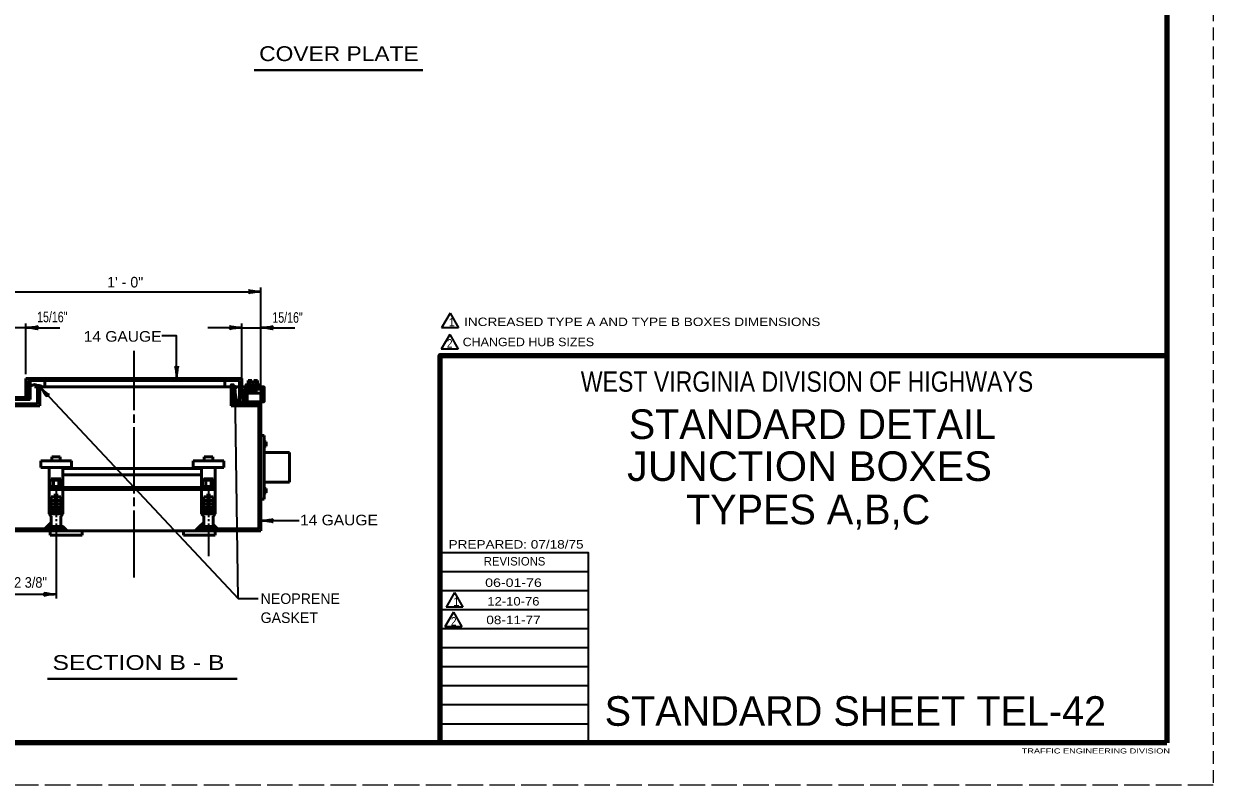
# Model space of a CAD drawing. Extents: x -1 to 679, y 0 to 440.
# Drawn here: x 397.8 to 678.8, y 0.4 to 180.3 of the extents above; entities that cross this region are included whole.
import ezdxf
from ezdxf.enums import TextEntityAlignment as Align

# ---------------------------------------------------------------- set-up
doc = ezdxf.new("R2010")
doc.units = 0
doc.linetypes.add('LONG_DASHED', pattern=[7.5, 6, -1.5])
doc.linetypes.add('MEDIUM_DASHED', pattern=[4.5, 3, -1.5])
doc.layers.add('1', color=7, linetype='Continuous', lineweight=53)
doc.layers.add('61', color=7, linetype='Continuous', lineweight=35)

msp = doc.modelspace()

# ---------------------------------------------------------------- linework, layer by layer
at = {"layer": '1', "linetype": 'MEDIUM_DASHED', "lineweight": 13}
msp.add_line((678.783, 440.398), (678.763, 0.378), dxfattribs=at)
at = {"layer": '1', "lineweight": 40}
for p, q in [((452.219, 169.353), (492.059, 169.353)), ((403.381, 25.473), (448.187, 25.473))]:
    msp.add_line(p, q, dxfattribs=at)
at = {"layer": '1', "lineweight": 35}
for p, q in [((393.265, 116.975), (453.765, 116.975)), ((453.765, 92.975), (453.765, 117.975)), ((498.479, 111.937), (496.479, 108.472)), ((498.479, 111.937), (500.479, 108.472)), ((398.265, 108.475), (393.265, 108.475)), ((398.265, 97.475), (398.265, 109.475)), ((398.265, 108.475), (406.265, 108.475)), ((449.265, 108.475), (441.265, 108.475)), ((449.265, 96.475), (449.265, 109.475)), ((449.265, 108.475), (453.765, 108.475)), ((453.765, 108.475), (461.765, 108.475)), ((498.402, 106.871), (496.402, 103.407)), ((500.479, 108.472), (496.479, 108.472)), ((498.402, 106.871), (500.402, 103.407)), ((423.765, 102.975), (423.765, 88.975)), ((500.402, 103.407), (496.402, 103.407)), ((423.765, 87.975), (423.765, 85.975)), ((423.765, 84.975), (423.765, 69.309)), ((405.39, 70.225), (405.39, 64.475)), ((423.765, 68.309), (423.765, 66.309)), ((441.39, 70.225), (441.39, 63.725)), ((423.765, 65.309), (423.765, 49.475)), ((405.39, 64.475), (405.39, 63.725)), ((405.39, 63.225), (405.39, 62.725)), ((405.39, 62.225), (405.39, 61.475)), ((441.39, 63.225), (441.39, 62.725)), ((441.39, 62.225), (441.39, 54.475)), ((453.765, 62.888), (462.798, 62.888)), ((405.39, 61.475), (405.39, 44.475)), ((531.163, 50.798), (496.183, 50.798)), ((393.265, 45.475), (405.39, 45.475)), ((531.163, 46.298), (496.183, 46.298)), ((499.52, 45.866), (497.52, 42.402)), ((499.52, 45.866), (501.52, 42.402)), ((448.434, 44.474), (453.113, 44.474)), ((501.52, 42.402), (497.52, 42.402)), ((531.163, 41.798), (496.183, 41.798)), ((499.278, 41.265), (497.278, 37.801)), ((499.278, 41.265), (501.278, 37.801)), ((531.163, 37.278), (496.183, 37.278)), ((501.278, 37.801), (497.278, 37.801)), ((531.163, 32.798), (496.183, 32.798)), ((531.163, 28.318), (496.183, 28.318)), ((531.163, 23.818), (496.183, 23.818)), ((531.163, 19.318), (496.183, 19.318)), ((531.163, 14.798), (496.183, 14.798))]:
    msp.add_line(p, q, dxfattribs=at)
at = {"layer": '1'}
for p, q in [((398.265, 96.475), (449.265, 96.475)), ((398.265, 96.475), (398.265, 91.975)), ((398.765, 95.975), (448.765, 95.975)), ((398.765, 95.975), (398.765, 91.975)), ((399.265, 95.975), (399.265, 91.475)), ((399.515, 96.475), (399.515, 95.975)), ((400.765, 96.475), (400.765, 95.975)), ((402.015, 96.475), (402.015, 95.975)), ((402.765, 95.975), (402.765, 94.478)), ((403.265, 96.475), (403.265, 95.975)), ((404.515, 96.475), (404.515, 95.975)), ((405.765, 96.475), (405.765, 95.975)), ((407.015, 96.475), (407.015, 95.975)), ((408.265, 96.475), (408.265, 95.975)), ((409.515, 96.475), (409.515, 95.975)), ((410.765, 96.475), (410.765, 95.975)), ((412.015, 96.475), (412.015, 95.975)), ((413.265, 96.475), (413.265, 95.975)), ((414.515, 96.475), (414.515, 95.975)), ((415.765, 96.475), (415.765, 95.975)), ((417.015, 96.475), (417.015, 95.975)), ((418.265, 96.475), (418.265, 95.975)), ((419.515, 96.475), (419.515, 95.975)), ((420.765, 96.475), (420.765, 95.975)), ((422.015, 96.475), (422.015, 95.975)), ((423.265, 96.475), (423.265, 95.975)), ((424.515, 96.475), (424.515, 95.975)), ((425.765, 96.475), (425.765, 95.975)), ((427.015, 96.475), (427.015, 95.975)), ((428.265, 96.475), (428.265, 95.975)), ((429.515, 96.475), (429.515, 95.975)), ((430.765, 96.475), (430.765, 95.975)), ((432.015, 96.475), (432.015, 95.975)), ((433.265, 96.475), (433.265, 95.975)), ((434.515, 96.475), (434.515, 95.975)), ((435.765, 96.475), (435.765, 95.975)), ((437.015, 96.475), (437.015, 95.975)), ((438.265, 96.475), (438.265, 95.975)), ((439.515, 96.475), (439.515, 95.975)), ((440.765, 96.475), (440.765, 95.975)), ((442.015, 96.475), (442.015, 95.975)), ((443.265, 96.475), (443.265, 95.975)), ((444.515, 96.475), (444.515, 95.975)), ((445.265, 95.975), (445.265, 94.478)), ((445.765, 96.475), (445.765, 95.975)), ((447.015, 96.475), (447.015, 95.975)), ((448.265, 96.475), (448.265, 95.975)), ((448.765, 95.975), (448.765, 90.975)), ((449.265, 96.475), (449.265, 91.475)), ((450.765, 94.975), (450.765, 95.975)), ((450.765, 95.975), (451.64, 95.975)), ((451.203, 95.975), (451.203, 94.975)), ((451.64, 95.975), (451.64, 95.475)), ((453.015, 95.975), (452.14, 95.975)), ((452.14, 95.975), (452.14, 95.475)), ((452.578, 95.975), (452.578, 94.975)), ((453.015, 94.975), (453.015, 95.975)), ((401.515, 94.475), (400.265, 94.475)), ((401.015, 94.475), (401.015, 90.475)), ((401.515, 94.475), (401.515, 89.975)), ((402.015, 94.478), (448.765, 94.478)), ((447.265, 94.562), (447.765, 94.562)), ((447.265, 94.062), (447.765, 94.062)), ((447.765, 94.562), (447.765, 94.062)), ((450.515, 92.975), (453.765, 92.975)), ((451.64, 95.475), (452.14, 95.475)), ((453.515, 94.975), (453.515, 94.475)), ((401.515, 89.975), (393.765, 89.975)), ((399.265, 91.975), (395.265, 91.975)), ((399.265, 91.475), (395.265, 91.475)), ((401.015, 90.475), (395.265, 90.475)), ((398.515, 90.475), (398.515, 89.975)), ((400.015, 90.475), (400.015, 89.975)), ((453.265, 89.975), (446.765, 89.975)), ((453.765, 90.975), (447.265, 90.975)), ((453.765, 90.475), (447.265, 90.475)), ((448.765, 90.475), (448.765, 89.975)), ((449.265, 90.975), (449.265, 90.475)), ((450.265, 90.475), (450.265, 89.975)), ((450.765, 90.975), (450.765, 90.475)), ((451.765, 90.475), (451.765, 89.975)), ((452.265, 90.975), (452.265, 90.475)), ((453.103, 90.475), (453.103, 89.975)), ((453.265, 89.975), (453.265, 60.975)), ((453.765, 88.975), (453.265, 88.975)), ((453.765, 87.475), (453.265, 87.475)), ((453.765, 85.975), (453.265, 85.975)), ((453.765, 84.475), (453.265, 84.475)), ((453.765, 82.975), (453.265, 82.975)), ((454.515, 82.975), (453.765, 82.975)), ((454.515, 82.975), (454.515, 67.975)), ((453.765, 81.475), (453.265, 81.475)), ((453.765, 79.975), (453.265, 79.975)), ((454.515, 81.475), (455.015, 81.475)), ((454.515, 80.475), (455.015, 80.475)), ((454.515, 78.975), (460.515, 78.975)), ((455.015, 81.475), (455.015, 80.475)), ((460.515, 78.975), (460.515, 71.975)), ((401.765, 76.975), (409.015, 76.975)), ((401.765, 76.975), (401.765, 75.475)), ((404.39, 76.975), (404.39, 77.975)), ((404.39, 77.975), (406.39, 77.975)), ((406.39, 76.975), (406.39, 77.975)), ((409.015, 76.975), (409.015, 75.475)), ((437.765, 76.975), (445.015, 76.975)), ((437.765, 76.975), (437.765, 75.475)), ((440.39, 76.975), (440.39, 77.975)), ((440.39, 77.975), (442.39, 77.975)), ((442.39, 76.975), (442.39, 77.975)), ((445.015, 76.975), (445.015, 75.475)), ((453.765, 78.475), (453.265, 78.475)), ((453.765, 76.975), (453.265, 76.975)), ((401.765, 75.475), (409.015, 75.475)), ((403.765, 64.475), (403.765, 75.475)), ((407.015, 64.475), (407.015, 75.475)), ((407.015, 75.238), (439.765, 75.238)), ((407.015, 73.738), (439.765, 73.738)), ((437.765, 75.475), (445.015, 75.475)), ((439.765, 64.475), (439.765, 75.475)), ((443.015, 64.475), (443.015, 75.475)), ((453.765, 75.475), (453.265, 75.475)), ((453.765, 73.975), (453.265, 73.975)), ((403.765, 70.725), (407.015, 70.725)), ((404.015, 72.475), (404.265, 72.725)), ((404.015, 72.475), (406.765, 72.475)), ((404.015, 70.975), (404.015, 72.475)), ((404.015, 70.975), (406.765, 70.975)), ((404.265, 72.725), (406.515, 72.725)), ((404.765, 70.975), (404.765, 72.475)), ((406.015, 70.975), (406.015, 72.475)), ((406.515, 72.725), (406.765, 72.475)), ((406.765, 70.975), (406.765, 72.475)), ((407.015, 70.725), (440.015, 70.725)), ((439.765, 70.725), (443.015, 70.725)), ((440.015, 72.475), (440.265, 72.725)), ((440.015, 72.475), (442.765, 72.475)), ((440.015, 70.975), (440.015, 72.475)), ((440.015, 70.975), (442.765, 70.975)), ((440.265, 72.725), (442.515, 72.725)), ((440.765, 70.975), (440.765, 72.475)), ((442.015, 70.975), (442.015, 72.475)), ((442.515, 72.725), (442.765, 72.475)), ((442.765, 70.975), (442.765, 72.475)), ((453.765, 72.475), (453.265, 72.475)), ((453.765, 70.975), (453.265, 70.975)), ((454.515, 71.975), (460.515, 71.975)), ((454.515, 70.475), (455.015, 70.475)), ((455.015, 70.475), (455.015, 69.475)), ((403.765, 70.225), (407.015, 70.225)), ((404.265, 65.475), (404.265, 68.475)), ((404.265, 68.475), (406.515, 68.475)), ((404.265, 67.675), (406.515, 67.675)), ((404.89, 68.875), (405.89, 68.875)), ((404.89, 68.075), (405.89, 68.075)), ((406.515, 65.475), (406.515, 68.475)), ((407.015, 70.225), (440.015, 70.225)), ((439.765, 70.225), (443.015, 70.225)), ((440.265, 65.475), (440.265, 68.475)), ((440.265, 68.475), (442.515, 68.475)), ((440.265, 67.675), (442.515, 67.675)), ((440.89, 68.875), (441.89, 68.875)), ((440.89, 68.075), (441.89, 68.075)), ((442.515, 65.475), (442.515, 68.475)), ((453.765, 69.475), (453.265, 69.475)), ((453.765, 67.975), (453.265, 67.975)), ((454.515, 67.975), (453.765, 67.975)), ((454.515, 69.475), (455.015, 69.475)), ((403.765, 65.475), (407.015, 65.475)), ((403.765, 64.975), (407.015, 64.975)), ((404.265, 66.875), (406.515, 66.875)), ((404.265, 66.075), (406.515, 66.075)), ((404.89, 67.275), (405.89, 67.275)), ((404.89, 66.475), (405.89, 66.475)), ((439.765, 65.475), (443.015, 65.475)), ((439.765, 64.975), (443.015, 64.975)), ((440.265, 66.875), (442.515, 66.875)), ((440.265, 66.075), (442.515, 66.075)), ((440.89, 67.275), (441.89, 67.275)), ((440.89, 66.475), (441.89, 66.475)), ((453.765, 66.475), (453.265, 66.475)), ((453.765, 64.975), (453.265, 64.975)), ((403.265, 61.475), (404.265, 62.475)), ((403.765, 64.475), (407.015, 64.475)), ((404.265, 63.975), (403.765, 64.475)), ((404.265, 63.975), (404.265, 61.475)), ((406.515, 63.975), (407.015, 64.475)), ((406.515, 63.975), (406.515, 61.475)), ((438.265, 60.475), (440.265, 62.475)), ((439.765, 64.475), (443.015, 64.475)), ((440.265, 63.975), (439.765, 64.475)), ((442.515, 63.975), (443.015, 64.475)), ((442.515, 63.975), (442.515, 61.475)), ((442.515, 61.975), (443.015, 61.475)), ((453.765, 63.475), (453.265, 63.475)), ((453.765, 61.975), (453.265, 61.975)), ((398.265, 60.975), (398.265, 60.475)), ((399.765, 60.975), (399.765, 60.475)), ((401.265, 60.975), (401.265, 60.475)), ((403.265, 61.475), (402.765, 60.975)), ((402.765, 60.975), (402.765, 60.475)), ((403.265, 61.475), (403.265, 60.475)), ((403.265, 61.475), (407.015, 61.475)), ((404.015, 60.475), (404.015, 59.475)), ((404.015, 59.475), (411.515, 59.475)), ((407.015, 61.475), (408.015, 60.475)), ((411.515, 60.475), (411.515, 59.475)), ((435.515, 60.475), (435.515, 59.475)), ((443.015, 59.475), (435.515, 59.475)), ((439.265, 61.475), (438.265, 60.475)), ((439.265, 61.475), (443.015, 61.475)), ((439.265, 60.975), (443.015, 60.975)), ((443.015, 61.013), (443.015, 61.475)), ((443.015, 61.475), (443.515, 60.975)), ((453.265, 60.975), (443.015, 60.975)), ((443.015, 60.475), (443.015, 59.475)), ((444.765, 60.975), (444.765, 60.475)), ((446.265, 60.975), (446.265, 60.475)), ((447.765, 60.975), (447.765, 60.475)), ((449.265, 60.975), (449.265, 60.475)), ((450.765, 60.975), (450.765, 60.475)), ((452.265, 60.975), (452.265, 60.475))]:
    msp.add_line(p, q, dxfattribs=at)
at = {"layer": '1', "lineweight": 35}
for points in [[(433.874, 96.475), (433.874, 106.521), (430.407, 106.521)], [(401.515, 94.475), (448.434, 44.474), (447.734, 94.062)], [(531.163, 10.318), (531.163, 55.278), (496.183, 55.278)]]:
    msp.add_lwpolyline(points, dxfattribs=at)
at = {"layer": '1', "lineweight": 158}
msp.add_lwpolyline([(496.163, 10.358), (496.163, 101.938), (667.823, 101.938)], dxfattribs=at)
at = {"layer": '1'}
for points in [[(446.765, 89.975), (446.765, 94.975), (447.265, 94.975), (447.265, 89.975)], [(449.265, 91.475), (450.015, 91.475), (450.015, 93.975), (454.015, 93.975), (454.015, 90.975), (454.515, 90.975), (454.515, 94.475), (449.265, 94.475)], [(453.515, 94.975), (450.265, 94.975), (450.265, 94.475)], [(450.515, 90.975), (450.515, 93.475), (453.015, 93.475)], [(453.765, 92.975), (453.765, 82.975), (453.765, 67.975), (453.765, 60.475)], [(440.265, 63.975), (440.265, 61.475), (439.265, 61.475), (440.265, 62.475), (440.265, 61.475)], [(393.265, 60.475), (408.015, 60.475), (435.515, 60.475)], [(393.765, 60.975), (403.265, 60.975), (407.015, 60.975)], [(453.765, 60.475), (439.265, 60.475), (411.515, 60.475)], [(443.015, 61.475), (443.015, 60.475), (443.015, 60.945)]]:
    msp.add_lwpolyline(points, dxfattribs=at)
for points in [[(403.265, 61.475), (404.265, 62.475), (404.265, 61.475)], [(442.515, 61.475), (442.515, 61.975), (443.015, 61.475)], [(403.265, 60.975), (402.765, 60.975), (403.265, 61.475)], [(407.015, 60.475), (407.015, 61.475), (408.015, 60.475)], [(438.265, 60.475), (439.265, 61.475), (439.265, 60.475)], [(443.015, 60.975), (443.015, 61.475), (443.515, 60.975)]]:
    msp.add_lwpolyline(points, close=True, dxfattribs=at)
at = {"layer": '1', "lineweight": 40}
for centre, major_axis, ratio, start_param, end_param in [((452.674, 116.699), (1.786, 0.156), 0.122415, 0.8963533, 3.1415927), ((452.645, 117.187), (1.756, -0.176), 0.07063, 3.1407148, 5.41811), ((399.356, 108.751), (-1.786, -0.156), 0.122415, 0.8963533, 3.1415927), ((399.386, 108.264), (-1.756, 0.176), 0.07063, 3.1407148, 5.41811), ((448.174, 108.199), (1.786, 0.156), 0.122415, 0.8963533, 3.1415927), ((448.145, 108.687), (1.756, -0.176), 0.07063, 3.1407148, 5.41811), ((454.856, 108.751), (-1.786, -0.156), 0.122415, 0.8963533, 3.1415927), ((454.886, 108.264), (-1.756, 0.176), 0.07063, 3.1407148, 5.41811), ((433.598, 97.566), (0.156, -1.786), 0.122415, 0.8963533, 3.1415927), ((433.598, 97.566), (0.156, -1.786), 0.122415, 0.8963533, 3.1415927), ((434.086, 97.596), (-0.176, -1.756), 0.07063, 3.1407148, 5.41811), ((434.086, 97.596), (-0.176, -1.756), 0.07063, 3.1407148, 5.41811), ((402.128, 93.513), (1.074, -1.401), 0.07063, 6.2823074, 8.5597026), ((402.128, 93.513), (1.074, -1.401), 0.07063, 6.2823074, 8.5597026), ((402.463, 93.868), (-1.336, 1.195), 0.122415, 0.8963533, 3.1415927), ((402.463, 93.868), (-1.336, 1.195), 0.122415, 0.8963533, 3.1415927), ((447.538, 92.939), (-0.151, -1.759), 0.07063, 6.2823074, 8.5597026), ((448.025, 92.975), (-0.181, 1.783), 0.122415, 0.8963533, 3.1415927), ((454.856, 63.164), (-1.786, -0.156), 0.122415, 0.8963533, 3.1415927), ((454.886, 62.676), (-1.756, 0.176), 0.07063, 3.1407148, 5.41811), ((404.299, 45.199), (1.786, 0.156), 0.122415, 0.8963533, 3.1415927), ((404.299, 45.199), (1.786, 0.156), 0.122415, 0.8963533, 3.1415927), ((404.27, 45.687), (1.756, -0.176), 0.07063, 3.1407148, 5.41811), ((404.27, 45.687), (1.756, -0.176), 0.07063, 3.1407148, 5.41811)]:
    msp.add_ellipse(centre, major_axis=major_axis, ratio=ratio, start_param=start_param, end_param=end_param, dxfattribs=at)
at = {"layer": '1'}
msp.add_spline([(399.265, 94.725), (399.681, 94.836), (400.04, 94.945), (400.569, 94.992), (400.709, 94.883), (401.223, 94.789), (401.426, 94.789), (401.815, 94.696), (402.015, 94.478)], degree=3, dxfattribs=at)
at = {"layer": '61', "lineweight": 158}
for p, q in [((667.803, 430.398), (667.823, 10.358)), ((667.823, 10.358), (28.763, 10.378))]:
    msp.add_line(p, q, dxfattribs=at)
at = {"layer": '61', "linetype": 'LONG_DASHED', "lineweight": 13}
msp.add_line((678.763, 0.378), (-1.297, 0.358), dxfattribs=at)

# ---------------------------------------------------------------- texts
at = {"layer": '1'}
for s, height, width, p in [('COVER PLATE', 3.5, 1.15, (453.374, 171.477)), ('15/16"', 2.5, 0.75, (400.911, 109.758)), ('15/16"', 2.5, 0.75, (456.494, 109.637)), ('INCREASED TYPE A AND TYPE B BOXES DIMENSIONS', 2, 1.2, (501.791, 108.861)), ('14 GAUGE', 2.5, 1.1, (411.907, 105.165)), ('2', 2, 0.9, (497.718, 103.767)), ('CHANGED HUB SIZES', 2, 1.1, (501.451, 104.107)), ('14 GAUGE', 2.5, 1.1, (463.02, 61.771)), ('PREPARED: 07/18/75', 1.998, 1.2, (498.123, 56.278)), ('2 3/8"', 2.5, 0.9, (395.473, 47.024)), ('2', 2, 0.9, (498.666, 38.087)), ('SECTION B - B', 3.5, 1.25, (404.535, 27.597)), ('TRAFFIC ENGINEERING DIVISION', 1.2, 1.35, (633.543, 7.858))]:
    msp.add_text(s, height=height, dxfattribs=dict(at, width=width)).set_placement(p)
for s, height, p in [('1\' - 0"', 2.5, (417.465, 117.977)), ('1', 2, (498.142, 108.776)), ('REVISIONS', 1.998, (506.443, 52.278)), ('NEOPRENE', 2.5, (453.715, 43.195)), ('1', 2, (499.225, 42.725)), ('GASKET', 2.5, (453.715, 38.695)), ('STANDARD SHEET TEL-42', 6.993, (535.003, 14.398))]:
    msp.add_text(s, height=height, dxfattribs=at).set_placement(p)
for s, height, width, p in [('WEST VIRGINIA DIVISION OF HIGHWAYS', 4.795, 0.85, (582.812, 93.338)), ('JUNCTION BOXES', 6.993, 1.05, (583.394, 72.263)), ('06-01-76', 2, 1.25, (513.463, 47.218)), ('12-10-76', 2, 1.15, (513.443, 42.818)), ('08-11-77', 2, 1.2, (513.463, 38.418))]:
    msp.add_text(s, height=height, dxfattribs=dict(at, width=width)).set_placement(p, align=Align.CENTER)
for s, p in [('STANDARD DETAIL', (584.08, 82.178)), ('TYPES A,B,C', (583.074, 62.027))]:
    msp.add_text(s, height=6.993, dxfattribs=at).set_placement(p, align=Align.CENTER)

doc.saveas('drawing.dxf')
